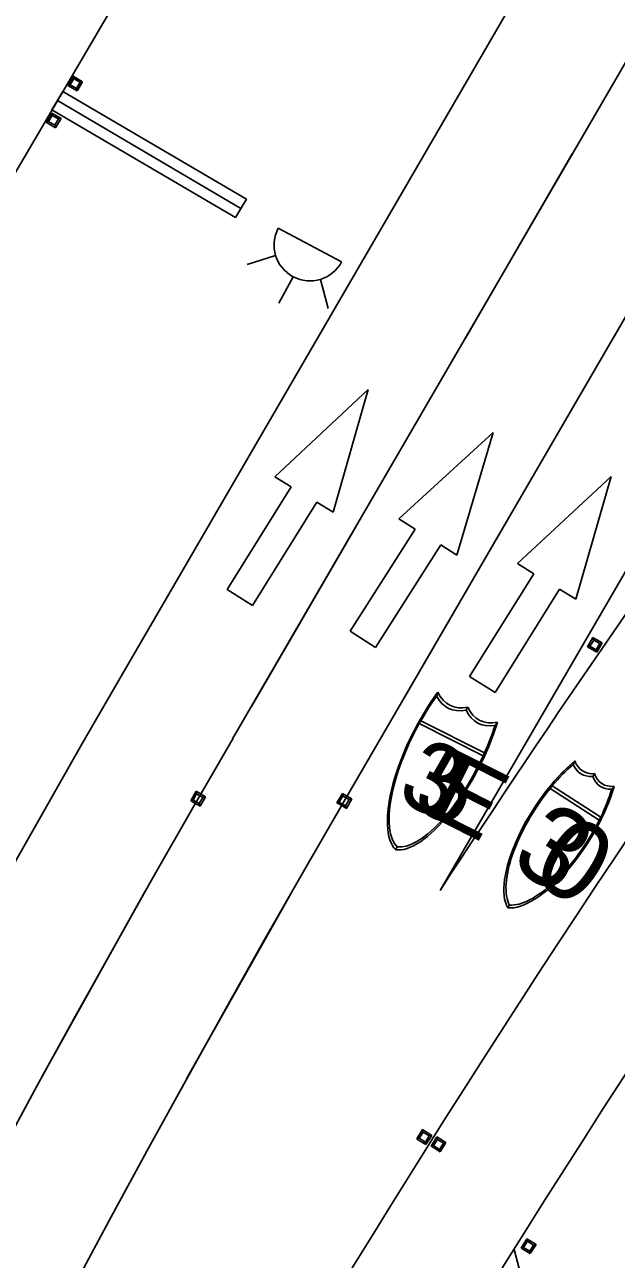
# Model space of a CAD drawing. Extents: x 2471014 to 2497726, y 6959577 to 6980268.
# Drawn here: x 2488611.6 to 2488667.2, y 6964209.1 to 6964325 of the extents above; entities that cross this region are included whole.
import ezdxf

# ---------------------------------------------------------------- set-up
doc = ezdxf.new("R2010")
doc.units = 0
for name, color, linetype in [('13', 7, 'Continuous'), ('18', 7, 'Continuous'), ('23', 7, 'Continuous'), ('25', 7, 'Continuous'), ('5', 7, 'Continuous'), ('ALIGN_ML_IH35_NB_SB', 7, 'Continuous'), ('G-GRID-MAJR', 7, 'Continuous'), ('PMK_Del_D-SY_SZ_TYC_CTB', 7, 'Continuous'), ('PMK_Pav_Mark_Multi_Shield', 7, 'Continuous'), ('PMK_Pav_Marker_TY I C', 7, 'Continuous'), ('RDWY_PAVE_XSTREET_FOC', 7, 'Continuous'), ('S-BRDG-DECK', 7, 'Continuous'), ('V7_25', 7, 'Continuous')]:
    doc.layers.add(name, color=color, linetype=linetype)

msp = doc.modelspace()

# ---------------------------------------------------------------- linework, layer by layer
at = {"layer": '13'}
msp.add_line((2488620.75, 6964263.98), (2489501.89, 6965780.24), dxfattribs=at)
msp.add_arc((2489874.44, 6963535.43), 1450, 149.83805, 187.72757, dxfattribs=at)
at = {"layer": '18'}
msp.add_line((2488593.6, 6964281.93), (2488654.25, 6964385.31), dxfattribs=at)
msp.add_arc((2489916.91, 6963512.7), 1400, 142.23979, 191.359, dxfattribs=at)
at = {"layer": '23'}
for p, q in [((2488664.46, 6964266.57), (2488664.97, 6964267.45)), ((2488665.61, 6964267.07), (2488664.97, 6964267.45)), ((2488664.97, 6964267.45), (2488665.04, 6964267.21)), ((2488665.04, 6964267.21), (2488665.62, 6964266.87)), ((2488665.84, 6964266.94), (2488665.33, 6964266.06)), ((2488665.84, 6964266.94), (2488665.61, 6964267.07)), ((2488665.62, 6964266.87), (2488665.84, 6964266.94)), ((2488664.69, 6964266.63), (2488664.46, 6964266.57)), ((2488664.46, 6964266.57), (2488665.33, 6964266.06)), ((2488665.16, 6964266.36), (2488664.69, 6964266.63)), ((2488665.28, 6964266.29), (2488665.16, 6964266.36)), ((2488665.33, 6964266.06), (2488665.28, 6964266.29)), ((2488627.19, 6964252.13), (2488627.7, 6964253.01)), ((2488627.41, 6964252.19), (2488627.19, 6964252.13)), ((2488627.19, 6964252.13), (2488627.43, 6964251.99)), ((2488628, 6964251.86), (2488627.41, 6964252.19)), ((2488627.43, 6964251.99), (2488628.07, 6964251.62)), ((2488628.58, 6964252.5), (2488627.7, 6964253.01)), ((2488627.7, 6964253.01), (2488627.75, 6964252.78)), ((2488627.75, 6964252.78), (2488627.87, 6964252.71)), ((2488627.87, 6964252.71), (2488628.34, 6964252.44)), ((2488628.07, 6964251.62), (2488628, 6964251.86)), ((2488628.58, 6964252.5), (2488628.07, 6964251.62)), ((2488628.34, 6964252.44), (2488628.58, 6964252.5)), ((2488640.93, 6964251.92), (2488641.44, 6964252.8)), ((2488641.15, 6964251.99), (2488640.93, 6964251.92)), ((2488640.93, 6964251.92), (2488641.17, 6964251.79)), ((2488641.74, 6964251.65), (2488641.15, 6964251.99)), ((2488642.32, 6964252.29), (2488641.44, 6964252.8)), ((2488641.44, 6964252.8), (2488641.49, 6964252.57)), ((2488641.49, 6964252.57), (2488641.62, 6964252.5)), ((2488641.62, 6964252.5), (2488642.08, 6964252.23)), ((2488642.32, 6964252.29), (2488641.81, 6964251.41)), ((2488642.08, 6964252.23), (2488642.32, 6964252.29)), ((2488641.17, 6964251.79), (2488641.81, 6964251.41)), ((2488641.81, 6964251.41), (2488641.74, 6964251.65)), ((2488648.43, 6964220.39), (2488648.97, 6964221.25)), ((2488649.83, 6964220.71), (2488648.97, 6964221.25)), ((2488648.97, 6964221.25), (2488649.01, 6964221.02)), ((2488649.01, 6964221.02), (2488649.13, 6964220.94)), ((2488649.13, 6964220.94), (2488649.59, 6964220.66)), ((2488649.83, 6964220.71), (2488649.29, 6964219.85)), ((2488649.59, 6964220.66), (2488649.83, 6964220.71)), ((2488649.77, 6964219.71), (2488650.32, 6964220.57)), ((2488651.17, 6964220.03), (2488650.32, 6964220.57)), ((2488650.32, 6964220.57), (2488650.36, 6964220.34)), ((2488648.65, 6964220.45), (2488648.43, 6964220.39)), ((2488648.43, 6964220.39), (2488648.66, 6964220.24)), ((2488649.23, 6964220.08), (2488648.65, 6964220.45)), ((2488648.66, 6964220.24), (2488649.29, 6964219.85)), ((2488649.29, 6964219.85), (2488649.23, 6964220.08)), ((2488650, 6964219.76), (2488649.77, 6964219.71)), ((2488649.77, 6964219.71), (2488650, 6964219.56)), ((2488650.57, 6964219.4), (2488650, 6964219.76)), ((2488650, 6964219.56), (2488650.63, 6964219.17)), ((2488650.36, 6964220.34), (2488650.48, 6964220.26)), ((2488650.48, 6964220.26), (2488650.93, 6964219.98)), ((2488651.17, 6964220.03), (2488650.63, 6964219.17)), ((2488650.93, 6964219.98), (2488651.17, 6964220.03)), ((2488650.63, 6964219.17), (2488650.57, 6964219.4)), ((2488658.23, 6964210.14), (2488658.77, 6964211)), ((2488658.46, 6964210.2), (2488658.23, 6964210.14)), ((2488658.23, 6964210.14), (2488658.46, 6964210)), ((2488659.03, 6964209.84), (2488658.46, 6964210.2)), ((2488659.63, 6964210.46), (2488658.77, 6964211)), ((2488658.77, 6964211), (2488658.82, 6964210.77)), ((2488658.82, 6964210.77), (2488658.94, 6964210.7)), ((2488658.94, 6964210.7), (2488659.39, 6964210.42)), ((2488659.63, 6964210.46), (2488659.09, 6964209.61)), ((2488659.39, 6964210.42), (2488659.63, 6964210.46)), ((2488658.46, 6964210), (2488659.09, 6964209.61)), ((2488659.09, 6964209.61), (2488659.03, 6964209.84))]:
    msp.add_line(p, q, dxfattribs=at)
for points in [[(2488665.62, 6964266.87), (2488665.28, 6964266.29), (2488664.69, 6964266.63), (2488665.04, 6964267.21)], [(2488627.41, 6964252.19), (2488627.75, 6964252.78), (2488628.34, 6964252.44), (2488628, 6964251.86)], [(2488641.15, 6964251.99), (2488641.49, 6964252.57), (2488642.08, 6964252.23), (2488641.74, 6964251.65)], [(2488648.65, 6964220.45), (2488649.01, 6964221.02), (2488649.59, 6964220.66), (2488649.23, 6964220.08)], [(2488650, 6964219.76), (2488650.36, 6964220.34), (2488650.93, 6964219.98), (2488650.57, 6964219.4)], [(2488658.46, 6964210.2), (2488658.82, 6964210.77), (2488659.39, 6964210.42), (2488659.03, 6964209.84)]]:
    msp.add_lwpolyline(points, close=True, dxfattribs=at)
at = {"layer": '25'}
msp.add_line((2488650.61, 6964243.7), (2488735.14, 6964389.16), dxfattribs=at)
for centre, radius, start, end in [((2489916.91, 6963512.7), 1414, 142.23979, 154.2029), ((2489663.45, 6963581.69), 1210, 141.30547, 146.83097), ((2489663.45, 6963581.69), 1186, 141.30547, 151.87874)]:
    msp.add_arc(centre, radius, start, end, dxfattribs=at)
at = {"layer": '5'}
msp.add_arc((2489663.45, 6963581.69), 1198, 141.30547, 161.17883, dxfattribs=at)
at = {"layer": 'ALIGN_ML_IH35_NB_SB'}
for p, q in [((2488635.09, 6964282.54), (2488643.87, 6964290.72)), ((2488643.87, 6964290.72), (2488640.58, 6964279.2)), ((2488646.75, 6964278.59), (2488655.6, 6964286.69)), ((2488655.6, 6964286.69), (2488652.2, 6964275.19)), ((2488636.62, 6964281.59), (2488635.09, 6964282.54)), ((2488657.89, 6964274.39), (2488666.67, 6964282.56)), ((2488666.67, 6964282.56), (2488663.37, 6964271.04)), ((2488630.61, 6964271.94), (2488636.62, 6964281.59)), ((2488639.05, 6964280.15), (2488633, 6964270.45)), ((2488640.58, 6964279.2), (2488639.05, 6964280.15)), ((2488648.27, 6964277.62), (2488646.75, 6964278.59)), ((2488642.17, 6964268.03), (2488648.27, 6964277.62)), ((2488650.68, 6964276.16), (2488644.55, 6964266.52)), ((2488652.2, 6964275.19), (2488650.68, 6964276.16)), ((2488659.42, 6964273.43), (2488657.89, 6964274.39)), ((2488653.39, 6964263.79), (2488659.42, 6964273.43)), ((2488633, 6964270.45), (2488630.61, 6964271.94)), ((2488661.84, 6964271.99), (2488655.79, 6964262.3)), ((2488663.37, 6964271.04), (2488661.84, 6964271.99)), ((2488644.55, 6964266.52), (2488642.17, 6964268.03)), ((2488655.79, 6964262.3), (2488653.39, 6964263.79))]:
    msp.add_line(p, q, dxfattribs=at)
at = {"layer": 'G-GRID-MAJR'}
for p, q in [((2488615.18, 6964318.71), (2488614.16, 6964316.98)), ((2488632.42, 6964308.59), (2488615.18, 6964318.71)), ((2488614.16, 6964316.98), (2488631.41, 6964306.86)), ((2488631.41, 6964306.86), (2488632.42, 6964308.59)), ((2488657.56, 6964210.01), (2488661.99, 6964193.51))]:
    msp.add_line(p, q, dxfattribs=at)
at = {"layer": 'PMK_Del_D-SY_SZ_TYC_CTB'}
for p, q in [((2488641.37, 6964302.7), (2488635.41, 6964305.88)), ((2488635.16, 6964303.31), (2488632.48, 6964302.45)), ((2488636.8, 6964301.31), (2488635.48, 6964298.83)), ((2488639.37, 6964301.06), (2488640.09, 6964298.34))]:
    msp.add_line(p, q, dxfattribs=at)
msp.add_arc((2488638.39, 6964304.29), 3.37, 151.9258, 331.9258, dxfattribs=at)
at = {"layer": 'PMK_Pav_Mark_Multi_Shield'}
for p, q in [((2488650.3, 6964261.97), (2488650.41, 6964262.33)), ((2488650.3, 6964261.97), (2488650.41, 6964262.33)), ((2488653.2, 6964260.91), (2488653.06, 6964260.64)), ((2488648.8, 6964259.64), (2488648.65, 6964259.36)), ((2488648.65, 6964259.36), (2488654.66, 6964256.33)), ((2488654.79, 6964256.61), (2488648.8, 6964259.64)), ((2488655.78, 6964259.2), (2488656, 6964259.5)), ((2488656, 6964259.5), (2488655.78, 6964259.2)), ((2488654.79, 6964256.61), (2488654.66, 6964256.33)), ((2488654.66, 6964256.33), (2488654.79, 6964256.61)), ((2488663.12, 6964255.53), (2488663.28, 6964255.86)), ((2488663.28, 6964255.86), (2488663.12, 6964255.53)), ((2488663.28, 6964255.86), (2488663.28, 6964255.86)), ((2488665.12, 6964254.67), (2488664.95, 6964254.4)), ((2488664.95, 6964254.41), (2488665.12, 6964254.67)), ((2488661.14, 6964253.52), (2488660.94, 6964253.28)), ((2488660.94, 6964253.28), (2488665.56, 6964250.29)), ((2488665.7, 6964250.57), (2488661.14, 6964253.52)), ((2488666.96, 6964253.48), (2488666.73, 6964253.2)), ((2488666.96, 6964253.48), (2488666.73, 6964253.2)), ((2488665.7, 6964250.57), (2488665.56, 6964250.29)), ((2488665.56, 6964250.29), (2488665.7, 6964250.57)), ((2488646.44, 6964247.53), (2488646.58, 6964247.81)), ((2488657.14, 6964242.34), (2488656.97, 6964242.07))]:
    msp.add_line(p, q, dxfattribs=at)
for centre, major_axis, ratio, start_param, end_param in [((2488651.62, 6964256.73), (4.79, 9.48), 0.373432, 1.138774, 3.023674), ((2488658.3, 6964274.47), (6.76, 13.39), 0.373432, 2.857844, 3.425344), ((2488651.62, 6964256.73), (4.65, 9.2), 0.373432, 1.164604, 1.442074), ((2488658.29, 6964274.48), (6.91, 13.67), 0.373432, 2.877224, 3.420954), ((2488661.11, 6964273.06), (6.91, 13.67), 0.373432, 2.862234, 3.405964), ((2488661.1, 6964273.06), (6.76, 13.39), 0.373432, 2.857844, 3.425344), ((2488651.61, 6964256.73), (4.65, 9.2), 0.373432, 1.472354, 3.020104), ((2488650.78, 6964257.15), (4.79, 9.48), 0.373432, 3.259514, 5.144414), ((2488650.78, 6964257.15), (4.65, 9.2), 0.373432, 4.841111, 5.118585), ((2488650.78, 6964257.15), (4.65, 9.2), 0.373432, 3.263084, 4.810824), ((2488662.59, 6964249.38), (5.09, 7.87), 0.400296, 0.901794, 2.940234), ((2488662.59, 6964249.38), (4.92, 7.61), 0.400296, 0.924954, 1.269494), ((2488669.06, 6964262.8), (5.26, 8.13), 0.400296, 2.870004, 3.430874), ((2488669.07, 6964262.79), (5.09, 7.87), 0.400296, 2.845044, 3.438144), ((2488670.92, 6964261.6), (5.26, 8.13), 0.400296, 2.852314, 3.413184), ((2488670.91, 6964261.6), (5.09, 7.87), 0.400296, 2.845044, 3.438144), ((2488662.59, 6964249.37), (4.92, 7.61), 0.400296, 1.304694, 2.933384), ((2488661.33, 6964250.19), (5.09, 7.87), 0.400296, 3.342954, 5.381394), ((2488661.33, 6964250.19), (4.92, 7.61), 0.400296, 5.01369, 5.358233), ((2488661.33, 6964250.19), (4.92, 7.61), 0.400296, 3.349804, 4.978494)]:
    msp.add_ellipse(centre, major_axis=major_axis, ratio=ratio, start_param=start_param, end_param=end_param, dxfattribs=at)
at = {"layer": 'PMK_Pav_Marker_TY I C'}
for p, q in [((2488615.65, 6964319.26), (2488616.16, 6964320.14)), ((2488615.87, 6964319.33), (2488615.65, 6964319.26)), ((2488615.65, 6964319.26), (2488615.88, 6964319.13)), ((2488616.46, 6964318.98), (2488615.87, 6964319.33)), ((2488615.88, 6964319.13), (2488616.52, 6964318.75)), ((2488617.04, 6964319.62), (2488616.16, 6964320.14)), ((2488616.16, 6964320.14), (2488616.21, 6964319.91)), ((2488616.21, 6964319.91), (2488616.34, 6964319.84)), ((2488616.34, 6964319.84), (2488616.8, 6964319.57)), ((2488617.04, 6964319.62), (2488616.52, 6964318.75)), ((2488616.8, 6964319.57), (2488617.04, 6964319.62)), ((2488616.52, 6964318.75), (2488616.46, 6964318.98)), ((2488613.63, 6964315.81), (2488614.14, 6964316.68)), ((2488613.85, 6964315.87), (2488613.63, 6964315.81)), ((2488613.63, 6964315.81), (2488613.86, 6964315.67)), ((2488614.43, 6964315.53), (2488613.85, 6964315.87)), ((2488613.86, 6964315.67), (2488614.5, 6964315.3)), ((2488615.01, 6964316.17), (2488614.14, 6964316.68)), ((2488614.14, 6964316.68), (2488614.19, 6964316.46)), ((2488614.19, 6964316.46), (2488614.31, 6964316.39)), ((2488614.31, 6964316.39), (2488614.78, 6964316.12)), ((2488615.01, 6964316.17), (2488614.5, 6964315.3)), ((2488614.78, 6964316.12), (2488615.01, 6964316.17)), ((2488614.5, 6964315.3), (2488614.43, 6964315.53))]:
    msp.add_line(p, q, dxfattribs=at)
for points in [[(2488615.87, 6964319.33), (2488616.21, 6964319.91), (2488616.8, 6964319.57), (2488616.46, 6964318.98)], [(2488613.85, 6964315.87), (2488614.19, 6964316.46), (2488614.78, 6964316.12), (2488614.43, 6964315.53)]]:
    msp.add_lwpolyline(points, close=True, dxfattribs=at)
at = {"layer": 'RDWY_PAVE_XSTREET_FOC'}
for p, q in [((2488652.99, 6964295.56), (2488663.03, 6964312.85)), ((2488666.74, 6964295.34), (2488676.79, 6964312.64)), ((2488632.89, 6964260.97), (2488642.94, 6964278.27)), ((2488646.64, 6964260.76), (2488656.69, 6964278.05)), ((2488613.19, 6964226.16), (2488622.92, 6964243.63)), ((2488626.81, 6964226.02), (2488636.62, 6964243.45))]:
    msp.add_line(p, q, dxfattribs=at)
at = {"layer": 'S-BRDG-DECK'}
for p, q in [((2488597.93, 6964289.32), (2488654.27, 6964385.33)), ((2488631.91, 6964307.73), (2488614.67, 6964317.84))]:
    msp.add_line(p, q, dxfattribs=at)
at = {"layer": 'V7_25'}
for p, q in [((2488631.13, 6964257.95), (2489512.27, 6965774.21)), ((2488641.5, 6964251.92), (2489522.64, 6965768.18))]:
    msp.add_line(p, q, dxfattribs=at)
for radius in [1438, 1426]:
    msp.add_arc((2489874.44, 6963535.43), radius, 149.83805, 187.72757, dxfattribs=at)

# ---------------------------------------------------------------- texts
at = {"layer": 'PMK_Pav_Mark_Multi_Shield'}
for s, height, rotation, p in [('3', 6.67, 333.1948, (2488646.32, 6964252.37)), ('5', 6.67, 333.1948, (2488647.77, 6964251.64)), ('E', 6.67, 333.1948, (2488649.3, 6964250.87)), ('3', 7.5, 327.0955, (2488656.99, 6964246.16)), ('0', 7.5, 327.0955, (2488658.92, 6964244.91))]:
    msp.add_text(s, height=height, rotation=rotation, dxfattribs=at).set_placement(p)

doc.saveas('drawing.dxf')
